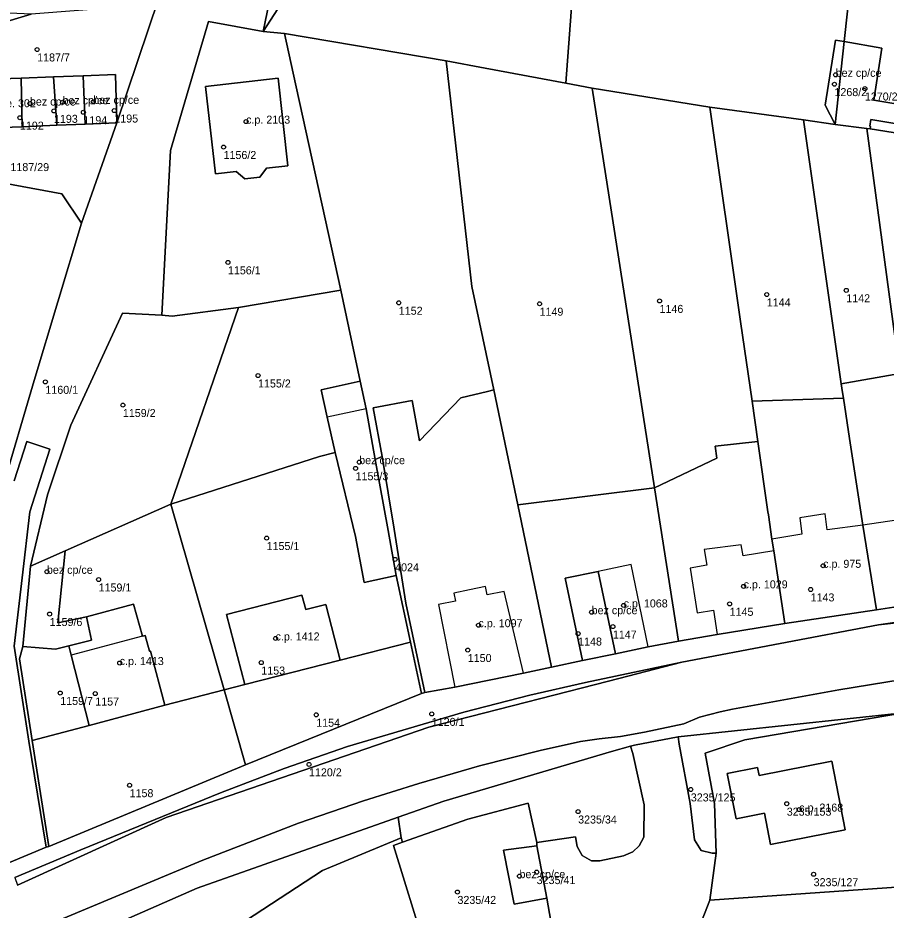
# Model space of a CAD drawing. Extents: x -878211 to -870363, y -1058464 to -1052522.
# Drawn here: x -875408.6 to -875300.1, y -1056399.9 to -1056288.4 of the extents above; entities that cross this region are included whole.
import ezdxf

# ---------------------------------------------------------------- set-up
doc = ezdxf.new("R2010")
doc.units = 0
for name, color, linetype in [('Definiční body', 7, 'Continuous'), ('Polygon budovy', 7, 'Continuous'), ('Polygon parcely', 7, 'Continuous')]:
    doc.layers.add(name, color=color, linetype=linetype)

msp = doc.modelspace()

# ---------------------------------------------------------------- linework, layer by layer
at = {"layer": 'Definiční body'}
for centre in [(-875406.21, -1056292.33994), (-875306.43, -1056295.49994), (-875306.58, -1056296.66994), (-875302.78, -1056297.21994), (-875407.11, -1056299.08994), (-875403.04, -1056298.92994), (-875399.19, -1056298.87994), (-875404.11, -1056300.00994), (-875400.43, -1056300.17994), (-875396.57, -1056299.96994), (-875408.36, -1056300.85994), (-875380.1, -1056301.34994), (-875382.92, -1056304.52994), (-875382.37, -1056318.93994), (-875305.1, -1056322.42994), (-875328.44, -1056323.75994), (-875315.04, -1056322.94994), (-875361.02, -1056323.98994), (-875343.43, -1056324.10994), (-875405.18, -1056333.86994), (-875378.61, -1056333.07994), (-875395.5, -1056336.76994), (-875365.97, -1056343.89994), (-875366.42, -1056344.66994), (-875377.54, -1056353.38994), (-875361.48, -1056356.04994), (-875307.99, -1056356.84994), (-875404.99, -1056357.59994), (-875398.53, -1056358.56994), (-875317.93, -1056359.41994), (-875309.56, -1056359.80994), (-875319.68, -1056361.60994), (-875404.65, -1056362.87994), (-875336.92, -1056362.64994), (-875332.92, -1056361.79994), (-875351.06, -1056364.26994), (-875334.27, -1056364.44994), (-875376.42, -1056365.92994), (-875338.61, -1056365.31994), (-875352.4, -1056367.37994), (-875395.89, -1056368.99994), (-875378.2, -1056368.94994), (-875403.33, -1056372.74994), (-875398.95, -1056372.81994), (-875371.34, -1056375.46994), (-875356.9, -1056375.35994), (-875372.24, -1056381.66994), (-875394.66, -1056384.26994), (-875324.53, -1056384.79994), (-875312.54, -1056386.57994), (-875310.99, -1056387.30994), (-875338.61, -1056387.55994), (-875343.79, -1056395.12994), (-875345.94, -1056395.62994), (-875309.18, -1056395.38994), (-875353.69, -1056397.60994)]:
    msp.add_circle(centre, 0.25, dxfattribs=at)
at = {"layer": 'Polygon budovy'}
for points in [[(-875305.37, -1056291.35), (-875306.43, -1056291.16), (-875307.75, -1056299.3), (-875306.51, -1056301.69), (-875302.54, -1056302.2), (-875302.13, -1056302.26), (-875302.08, -1056301.96), (-875302.18, -1056301.93), (-875302.04, -1056301.09), (-875295.32, -1056302.2), (-875294.92, -1056299.81), (-875301.66, -1056298.67), (-875300.65, -1056292.17)], [(-875400.44, -1056295.61), (-875404.17, -1056295.75), (-875403.75, -1056301.81), (-875400.2, -1056301.67)], [(-875400.44, -1056295.61), (-875400.2, -1056301.67), (-875396.26, -1056301.51), (-875396.44, -1056295.47)], [(-875408.21, -1056295.93), (-875412.12, -1056296.06), (-875411.83, -1056302.12), (-875408.09, -1056301.98)], [(-875408.09, -1056301.98), (-875403.75, -1056301.81), (-875404.17, -1056295.75), (-875408.21, -1056295.93)], [(-875376.1, -1056295.9), (-875385.18, -1056296.94), (-875383.94, -1056307.86), (-875381.34, -1056307.58), (-875380.24, -1056308.48), (-875378.37, -1056308.28), (-875377.55, -1056307.18), (-875374.88, -1056306.89)], [(-875369.99, -1056338.28), (-875368.95, -1056342.68), (-875366.42, -1056353.19), (-875365.35, -1056358.93), (-875361.33, -1056358.08), (-875362.36, -1056352.43), (-875363.96, -1056343.57), (-875365.1, -1056337.23)], [(-875314.41, -1056353.51), (-875314.15, -1056354.97), (-875312.78, -1056364.06), (-875301.34, -1056362.33), (-875303.05, -1056351.78), (-875307.48, -1056352.37), (-875307.75, -1056350.34), (-875310.9, -1056350.87), (-875310.66, -1056352.9)], [(-875298.81, -1056351.15), (-875303.05, -1056351.78), (-875301.34, -1056362.33), (-875294.27, -1056361.25), (-875295.94, -1056350.67)], [(-875324.61, -1056357.16), (-875323.75, -1056362.72), (-875321.7, -1056362.4), (-875321.25, -1056365.44), (-875312.78, -1056364.06), (-875314.15, -1056354.97), (-875317.99, -1056355.6), (-875318.22, -1056354.21), (-875322.86, -1056354.8), (-875322.52, -1056356.76)], [(-875407.06, -1056356.91), (-875407.98, -1056366.93), (-875403.93, -1056367.27), (-875402.25, -1056366.86), (-875399.41, -1056366.16), (-875400.04, -1056363.22), (-875403.63, -1056363.96), (-875402.69, -1056354.98)], [(-875329.85, -1056366.98), (-875331.97, -1056356.68), (-875336.12, -1056357.54), (-875333.92, -1056367.83)], [(-875340.21, -1056358.39), (-875338.05, -1056368.7), (-875333.92, -1056367.83), (-875336.12, -1056357.54)], [(-875350.18, -1056359.45), (-875352.17, -1056359.85), (-875354.16, -1056360.25), (-875353.95, -1056361.28), (-875356.06, -1056361.7), (-875354, -1056372.01), (-875345.45, -1056370.25), (-875347.86, -1056360.07), (-875349.97, -1056360.49)], [(-875382.53, -1056362.95), (-875380.25, -1056371.69), (-875368.36, -1056368.65), (-875370.14, -1056361.68), (-875372.65, -1056362.32), (-875373.13, -1056360.5)], [(-875392.16, -1056367.53), (-875392.7, -1056365.54), (-875393.06, -1056365.64), (-875401.95, -1056368.01), (-875399.69, -1056376.79), (-875390.25, -1056374.27), (-875392.06, -1056367.51)], [(-875319.97, -1056382.81), (-875318.88, -1056388.45), (-875315.34, -1056387.75), (-875314.57, -1056391.67), (-875305.25, -1056389.85), (-875306.91, -1056381.27), (-875315.99, -1056383.04), (-875316.18, -1056382.07)], [(-875343.77, -1056391.85), (-875347.92, -1056392.37), (-875346.61, -1056399.13), (-875342.54, -1056398.37)]]:
    msp.add_lwpolyline(points, close=True, dxfattribs=at)
at = {"layer": 'Polygon parcely'}
for points in [[(-875326.91, -1056259.71), (-875336.96, -1056259.61), (-875351.04, -1056263.15), (-875355.95, -1056264.37), (-875367.7, -1056267.24), (-875367.35, -1056268.89), (-875366.53, -1056272.35), (-875367.28, -1056273.5), (-875338.32, -1056272), (-875340.16, -1056296.55), (-875336.87, -1056297.17), (-875322.17, -1056299.55), (-875310.44, -1056301.13), (-875306.51, -1056301.69), (-875307.75, -1056299.3), (-875306.43, -1056291.16), (-875305.37, -1056291.35), (-875302.02, -1056260.98)], [(-875302.13, -1056302.26), (-875291.97, -1056303.86), (-875284.55, -1056269.53), (-875283.04, -1056262.38), (-875293.89, -1056266.2), (-875296.77, -1056265.83), (-875300.32, -1056264.94), (-875300.08, -1056262.78), (-875302.02, -1056260.98), (-875305.37, -1056291.35), (-875300.65, -1056292.17), (-875301.66, -1056298.67), (-875294.92, -1056299.81), (-875295.32, -1056302.2), (-875302.04, -1056301.09), (-875302.18, -1056301.93), (-875302.08, -1056301.96)], [(-875340.16, -1056296.55), (-875338.32, -1056272), (-875367.28, -1056273.5), (-875369.36, -1056276.73), (-875377.98, -1056290.07), (-875375.29, -1056290.34), (-875355.09, -1056293.74), (-875350.22, -1056294.66)], [(-875375.12, -1056276.33), (-875377.98, -1056290.07), (-875369.36, -1056276.73)], [(-875404.17, -1056295.75), (-875400.44, -1056295.61), (-875396.44, -1056295.47), (-875396.26, -1056301.51), (-875391.02, -1056285.88), (-875394.57, -1056286.98), (-875406.97, -1056287.91), (-875415.57, -1056290.51), (-875427.13, -1056290.52), (-875436.64, -1056290.52), (-875436.52, -1056296.94), (-875432.35, -1056296.72), (-875428.45, -1056296.53), (-875424.13, -1056296.4), (-875420.2, -1056296.3), (-875416.02, -1056296.19), (-875412.12, -1056296.06), (-875408.21, -1056295.93)], [(-875368.28, -1056322.39), (-875374.21, -1056295.28), (-875375.29, -1056290.34), (-875377.98, -1056290.07), (-875384.79, -1056288.85), (-875389.54, -1056304.94), (-875390.65, -1056325.55), (-875389.35, -1056325.65), (-875381.06, -1056324.59)], [(-875355.09, -1056293.74), (-875375.29, -1056290.34), (-875374.21, -1056295.28), (-875368.28, -1056322.39), (-875365.84, -1056333.77), (-875365.1, -1056337.23), (-875363.96, -1056343.57), (-875363.08, -1056343.2), (-875364.21, -1056337.1), (-875359.34, -1056336.21), (-875358.45, -1056341.25), (-875353.27, -1056335.87), (-875349.94, -1056335.06), (-875349.16, -1056334.87), (-875351.9, -1056321.95)], [(-875306.51, -1056301.69), (-875305.37, -1056291.35), (-875306.43, -1056291.16), (-875307.75, -1056299.3)], [(-875306.51, -1056301.69), (-875302.54, -1056302.2), (-875302.13, -1056302.26), (-875302.08, -1056301.96), (-875302.18, -1056301.93), (-875302.04, -1056301.09), (-875295.32, -1056302.2), (-875294.92, -1056299.81), (-875301.66, -1056298.67), (-875300.65, -1056292.17), (-875305.37, -1056291.35)], [(-875349.16, -1056334.87), (-875346.15, -1056349.25), (-875329.07, -1056347.09), (-875336.87, -1056297.17), (-875340.16, -1056296.55), (-875350.22, -1056294.66), (-875355.09, -1056293.74), (-875351.9, -1056321.95)], [(-875400.44, -1056295.61), (-875404.17, -1056295.75), (-875403.75, -1056301.81), (-875400.2, -1056301.67)], [(-875396.26, -1056301.51), (-875396.44, -1056295.47), (-875400.44, -1056295.61), (-875400.2, -1056301.67)], [(-875408.21, -1056295.93), (-875412.12, -1056296.06), (-875411.83, -1056302.12), (-875408.09, -1056301.98)], [(-875404.17, -1056295.75), (-875408.21, -1056295.93), (-875408.09, -1056301.98), (-875403.75, -1056301.81)], [(-875374.88, -1056306.89), (-875377.55, -1056307.18), (-875378.37, -1056308.28), (-875380.24, -1056308.48), (-875381.34, -1056307.58), (-875383.94, -1056307.86), (-875385.18, -1056296.94), (-875376.1, -1056295.9)], [(-875374.88, -1056306.89), (-875376.1, -1056295.9), (-875385.18, -1056296.94), (-875383.94, -1056307.86), (-875381.34, -1056307.58), (-875380.24, -1056308.48), (-875378.37, -1056308.28), (-875377.55, -1056307.18)], [(-875316.14, -1056341.31), (-875316.87, -1056336.26), (-875318.3, -1056326.31), (-875322.17, -1056299.55), (-875336.87, -1056297.17), (-875329.07, -1056347.09), (-875321.27, -1056343.39), (-875321.5, -1056341.9)], [(-875316.87, -1056336.26), (-875305.47, -1056335.92), (-875305.58, -1056335.18), (-875305.73, -1056334.13), (-875310.44, -1056301.13), (-875322.17, -1056299.55), (-875318.3, -1056326.31)], [(-875298.43, -1056332.82), (-875302.54, -1056302.2), (-875306.51, -1056301.69), (-875310.44, -1056301.13), (-875305.73, -1056334.13)], [(-875411.83, -1056302.12), (-875415.81, -1056302.28), (-875419.95, -1056302.44), (-875420.85, -1056302.48), (-875415.33, -1056308.13), (-875403.11, -1056310.38), (-875400.67, -1056314.05), (-875396.26, -1056301.51), (-875400.2, -1056301.67), (-875403.75, -1056301.81), (-875408.09, -1056301.98)], [(-875302.13, -1056302.26), (-875302.54, -1056302.2), (-875298.43, -1056332.82), (-875297.97, -1056336.46), (-875289.05, -1056336.42), (-875282.56, -1056335.7), (-875282.98, -1056331.54), (-875285.37, -1056305.08), (-875291.97, -1056303.86)], [(-875418.39, -1056347.04), (-875414.86, -1056347.4), (-875411.47, -1056347.74), (-875411.16, -1056348.42), (-875410.64, -1056347.42), (-875406.59, -1056333.71), (-875400.67, -1056314.05), (-875403.11, -1056310.38), (-875415.33, -1056308.13), (-875420.85, -1056302.48), (-875424.03, -1056302.61), (-875428.34, -1056302.78), (-875431.52, -1056302.9), (-875433.3, -1056345.53)], [(-875370.91, -1056343.17), (-875368.95, -1056342.68), (-875369.99, -1056338.28), (-875370.71, -1056334.85), (-875365.84, -1056333.77), (-875368.28, -1056322.39), (-875381.06, -1056324.59), (-875389.51, -1056349.15)], [(-875407.06, -1056356.91), (-875402.69, -1056354.98), (-875389.51, -1056349.15), (-875381.06, -1056324.59), (-875389.35, -1056325.65), (-875390.65, -1056325.55), (-875395.54, -1056325.27), (-875401.99, -1056339.26), (-875404.92, -1056347.98)], [(-875301.34, -1056362.33), (-875294.27, -1056361.25), (-875295.94, -1056350.67), (-875296.19, -1056349.09), (-875296.7, -1056345.43), (-875297.41, -1056340.42), (-875297.97, -1056336.46), (-875298.43, -1056332.82), (-875305.73, -1056334.13), (-875305.58, -1056335.18), (-875305.47, -1056335.92), (-875304.7, -1056340.96), (-875303.05, -1056351.78)], [(-875368.95, -1056342.68), (-875366.42, -1056353.19), (-875365.35, -1056358.93), (-875361.33, -1056358.08), (-875362.36, -1056352.43), (-875363.96, -1056343.57), (-875365.1, -1056337.23), (-875365.84, -1056333.77), (-875370.71, -1056334.85), (-875369.99, -1056338.28)], [(-875354, -1056372.01), (-875345.45, -1056370.25), (-875341.92, -1056369.5), (-875346.15, -1056349.25), (-875349.16, -1056334.87), (-875349.94, -1056335.06), (-875353.27, -1056335.87), (-875358.45, -1056341.25), (-875359.34, -1056336.21), (-875364.21, -1056337.1), (-875363.08, -1056343.2), (-875361.59, -1056352.27), (-875360.14, -1056361.53), (-875357.78, -1056372.69)], [(-875316.14, -1056341.31), (-875314.89, -1056350.12), (-875314.83, -1056350.46), (-875314.41, -1056353.51), (-875314.15, -1056354.97), (-875312.78, -1056364.06), (-875301.34, -1056362.33), (-875303.05, -1056351.78), (-875304.7, -1056340.96), (-875305.47, -1056335.92), (-875316.87, -1056336.26)], [(-875326.08, -1056366.26), (-875321.25, -1056365.44), (-875312.78, -1056364.06), (-875314.15, -1056354.97), (-875314.41, -1056353.51), (-875314.83, -1056350.46), (-875314.89, -1056350.12), (-875316.14, -1056341.31), (-875321.5, -1056341.9), (-875321.27, -1056343.39), (-875329.07, -1056347.09)], [(-875361.33, -1056358.08), (-875365.35, -1056358.93), (-875366.42, -1056353.19), (-875368.95, -1056342.68), (-875370.91, -1056343.17), (-875389.51, -1056349.15), (-875382.86, -1056372.36), (-875380.25, -1056371.69), (-875382.53, -1056362.95), (-875373.13, -1056360.5), (-875372.65, -1056362.32), (-875370.14, -1056361.68), (-875368.36, -1056368.65), (-875359.55, -1056366.4)], [(-875363.08, -1056343.2), (-875363.96, -1056343.57), (-875362.36, -1056352.43), (-875361.33, -1056358.08), (-875359.55, -1056366.4), (-875358.17, -1056372.82), (-875357.78, -1056372.69), (-875360.14, -1056361.53), (-875361.59, -1056352.27)], [(-875346.15, -1056349.25), (-875341.92, -1056369.5), (-875338.05, -1056368.7), (-875340.21, -1056358.39), (-875336.12, -1056357.54), (-875333.92, -1056367.83), (-875329.85, -1056366.98), (-875326.08, -1056366.26), (-875329.07, -1056347.09)], [(-875403.63, -1056363.96), (-875400.04, -1056363.22), (-875394.17, -1056361.65), (-875393.06, -1056365.64), (-875392.7, -1056365.54), (-875392.16, -1056367.53), (-875392.06, -1056367.51), (-875390.25, -1056374.27), (-875382.86, -1056372.36), (-875389.51, -1056349.15), (-875402.69, -1056354.98)], [(-875402.25, -1056366.86), (-875399.41, -1056366.16), (-875400.04, -1056363.22), (-875403.63, -1056363.96), (-875402.69, -1056354.98), (-875407.06, -1056356.91), (-875407.98, -1056366.93), (-875403.93, -1056367.27)], [(-875333.92, -1056367.83), (-875336.12, -1056357.54), (-875340.21, -1056358.39), (-875338.05, -1056368.7)], [(-875301.06, -1056364.21), (-875241.87, -1056357.54), (-875267.21, -1056359.9), (-875277.03, -1056360.91), (-875283.21, -1056361.69)], [(-875382.53, -1056362.95), (-875380.25, -1056371.69), (-875368.36, -1056368.65), (-875370.14, -1056361.68), (-875372.65, -1056362.32), (-875373.13, -1056360.5)], [(-875399.69, -1056376.79), (-875390.25, -1056374.27), (-875392.06, -1056367.51), (-875392.16, -1056367.53), (-875392.7, -1056365.54), (-875393.06, -1056365.64), (-875394.17, -1056361.65), (-875400.04, -1056363.22), (-875399.41, -1056366.16), (-875402.25, -1056366.86), (-875401.95, -1056368.01)], [(-875407.98, -1056366.93), (-875408.42, -1056368.46), (-875406.82, -1056378.69), (-875399.69, -1056376.79), (-875401.95, -1056368.01), (-875402.25, -1056366.86), (-875403.93, -1056367.27)], [(-875368.36, -1056368.65), (-875380.25, -1056371.69), (-875382.86, -1056372.36), (-875380.18, -1056381.71), (-875358.17, -1056372.82), (-875359.55, -1056366.4)], [(-875409.01, -1056395.8), (-875408.68, -1056396.75), (-875390.07, -1056388.31), (-875357.27, -1056377.02), (-875336.44, -1056371.66), (-875333.52, -1056370.91), (-875325.65, -1056368.89), (-875337.67, -1056371.42), (-875344.63, -1056373.02), (-875352.88, -1056375.12), (-875367.42, -1056379.44), (-875375.34, -1056382.19), (-875383.29, -1056385.23), (-875400.76, -1056392.35)], [(-875406.82, -1056378.69), (-875404.76, -1056391.92), (-875380.18, -1056381.71), (-875382.86, -1056372.36), (-875390.25, -1056374.27), (-875399.69, -1056376.79)], [(-875326.1, -1056378.2), (-875325.97, -1056379.15), (-875324.63, -1056386.54), (-875324.06, -1056391.07), (-875323.25, -1056392.41), (-875321.87, -1056392.75), (-875321.37, -1056392.77), (-875321.58, -1056386.56), (-875322.73, -1056380.24), (-875317.77, -1056378.59), (-875297.94, -1056375.24)], [(-875296.47, -1056396.84), (-875297.94, -1056375.24), (-875317.77, -1056378.59), (-875322.73, -1056380.24), (-875321.58, -1056386.56), (-875321.37, -1056392.77), (-875322.15, -1056398.63)], [(-875332.07, -1056379.37), (-875334.45, -1056380.07), (-875355.39, -1056386.25), (-875361.1, -1056388.27), (-875360.73, -1056390.83), (-875360.54, -1056391.37), (-875352.41, -1056388.49), (-875344.85, -1056386.51), (-875343.75, -1056391.44), (-875338.92, -1056390.7), (-875338.73, -1056391.94), (-875338.12, -1056393.03), (-875336.94, -1056393.7), (-875335.89, -1056393.73), (-875332.96, -1056393.1), (-875331.76, -1056392.58), (-875330.97, -1056391.83), (-875330.42, -1056390.75), (-875330.37, -1056386.7), (-875331.79, -1056380.31)], [(-875314.57, -1056391.67), (-875305.25, -1056389.85), (-875306.91, -1056381.27), (-875315.99, -1056383.04), (-875316.18, -1056382.07), (-875319.97, -1056382.81), (-875318.88, -1056388.45), (-875315.34, -1056387.75)], [(-875314.57, -1056391.67), (-875315.34, -1056387.75), (-875318.88, -1056388.45), (-875319.97, -1056382.81), (-875316.18, -1056382.07), (-875315.99, -1056383.04), (-875306.91, -1056381.27), (-875305.25, -1056389.85)], [(-875343.75, -1056391.44), (-875344.85, -1056386.51), (-875352.41, -1056388.49), (-875360.54, -1056391.37), (-875361.7, -1056391.81), (-875357.73, -1056404.64), (-875341.85, -1056402.19), (-875342.54, -1056398.37), (-875346.61, -1056399.13), (-875347.92, -1056392.37), (-875343.77, -1056391.85)], [(-875460.24, -1056430.33), (-875515.54, -1056452.4), (-875503.27, -1056450.06), (-875497.4, -1056449.08), (-875474.74, -1056447.47), (-875471.06, -1056446.94), (-875473.08, -1056441.99), (-875445.75, -1056437.14), (-875438.06, -1056434.12), (-875434.01, -1056431.54), (-875422.98, -1056424.06), (-875409.72, -1056417.39), (-875388.72, -1056406.79), (-875370.54, -1056394.92), (-875360.73, -1056390.83), (-875361.1, -1056388.27), (-875386.22, -1056397.14), (-875418.32, -1056411.2)], [(-875388.59, -1056413.05), (-875357.73, -1056404.64), (-875361.7, -1056391.81), (-875360.54, -1056391.37), (-875360.73, -1056390.83), (-875370.54, -1056394.92), (-875388.72, -1056406.79)], [(-875343.77, -1056391.85), (-875347.92, -1056392.37), (-875346.61, -1056399.13), (-875342.54, -1056398.37)], [(-875294.84, -1056413.39), (-875295.85, -1056405.83), (-875296.47, -1056396.84), (-875322.15, -1056398.63), (-875323.47, -1056402.06), (-875324.32, -1056403.89), (-875327.7, -1056411.12), (-875330.72, -1056421.11)]]:
    msp.add_lwpolyline(points, close=True, dxfattribs=at)
for points in [[(-875409.07, -1056346.25), (-875407.48, -1056341.33), (-875404.62, -1056342.29), (-875407.12, -1056350.09), (-875408.09, -1056358.35), (-875409.09, -1056366.89), (-875407.24, -1056378.74), (-875405.09, -1056391.99), (-875404.76, -1056391.92), (-875406.82, -1056378.69), (-875408.42, -1056368.46), (-875407.98, -1056366.93), (-875407.06, -1056356.91), (-875404.92, -1056347.98), (-875401.99, -1056339.26), (-875395.54, -1056325.27), (-875390.65, -1056325.55), (-875389.54, -1056304.94), (-875384.79, -1056288.85), (-875377.98, -1056290.07), (-875375.12, -1056276.33)], [(-875415.57, -1056290.51), (-875406.97, -1056287.91), (-875438.96, -1056286.41)], [(-875391.02, -1056285.88), (-875396.26, -1056301.51), (-875400.67, -1056314.05), (-875406.59, -1056333.71), (-875410.64, -1056347.42)], [(-875405.09, -1056391.99), (-875407.24, -1056378.74), (-875409.09, -1056366.89), (-875408.09, -1056358.35), (-875407.12, -1056350.09), (-875404.62, -1056342.29), (-875407.48, -1056341.33), (-875409.07, -1056346.25)], [(-875409.01, -1056395.8), (-875400.76, -1056392.35), (-875383.29, -1056385.23), (-875375.34, -1056382.19), (-875367.42, -1056379.44), (-875352.88, -1056375.12), (-875344.63, -1056373.02), (-875337.67, -1056371.42), (-875325.65, -1056368.89), (-875301.06, -1056364.21), (-875283.21, -1056361.69), (-875277.03, -1056360.91), (-875267.21, -1056359.9), (-875241.87, -1056357.54), (-875215.85, -1056355.72), (-875209.72, -1056355.65), (-875201.3, -1056355.92), (-875193.92, -1056356.66), (-875178.63, -1056358.65), (-875156.63, -1056364.33), (-875140.69, -1056370.83), (-875124.79, -1056378.79)], [(-875178.63, -1056358.65), (-875193.92, -1056356.66), (-875215.85, -1056355.72), (-875241.87, -1056357.54), (-875301.06, -1056364.21), (-875325.65, -1056368.89), (-875333.52, -1056370.91), (-875336.44, -1056371.66), (-875357.27, -1056377.02), (-875390.07, -1056388.31), (-875408.68, -1056396.75)], [(-875294.27, -1056361.25), (-875301.34, -1056362.33), (-875312.78, -1056364.06), (-875321.25, -1056365.44), (-875326.08, -1056366.26), (-875329.85, -1056366.98), (-875333.92, -1056367.83), (-875338.05, -1056368.7), (-875341.92, -1056369.5), (-875345.45, -1056370.25), (-875354, -1056372.01), (-875357.78, -1056372.69), (-875358.17, -1056372.82), (-875380.18, -1056381.71), (-875404.76, -1056391.92), (-875405.09, -1056391.99), (-875409.65, -1056393.92)], [(-875420.94, -1056408.41), (-875385.5, -1056393.63), (-875373.56, -1056389.01), (-875365.42, -1056386.2), (-875358.5, -1056384.03), (-875350.93, -1056381.86), (-875343.34, -1056379.91), (-875338.3, -1056378.82), (-875335.97, -1056378.46), (-875333.32, -1056378.17), (-875330.31, -1056377.63), (-875325.4, -1056376.6), (-875323.46, -1056375.78), (-875320.87, -1056375.1), (-875319.32, -1056374.78), (-875306.02, -1056372.36), (-875292.24, -1056370.08)], [(-875292.24, -1056370.08), (-875306.02, -1056372.36), (-875319.32, -1056374.78), (-875320.87, -1056375.1), (-875323.46, -1056375.78), (-875325.4, -1056376.6), (-875330.31, -1056377.63), (-875333.32, -1056378.17), (-875335.97, -1056378.46), (-875338.3, -1056378.82), (-875343.34, -1056379.91), (-875350.93, -1056381.86), (-875358.5, -1056384.03), (-875365.42, -1056386.2), (-875373.56, -1056389.01), (-875385.5, -1056393.63), (-875420.94, -1056408.41)], [(-875418.32, -1056411.2), (-875386.22, -1056397.14), (-875361.1, -1056388.27), (-875355.39, -1056386.25), (-875334.45, -1056380.07), (-875332.07, -1056379.37), (-875331.56, -1056379.27), (-875326.1, -1056378.2), (-875297.94, -1056375.24)], [(-875323.47, -1056402.06), (-875322.15, -1056398.63), (-875321.37, -1056392.77), (-875321.87, -1056392.75), (-875323.25, -1056392.41), (-875324.06, -1056391.07), (-875324.63, -1056386.54), (-875325.97, -1056379.15), (-875326.1, -1056378.2), (-875331.56, -1056379.27), (-875332.07, -1056379.37), (-875331.79, -1056380.31), (-875330.37, -1056386.7), (-875330.42, -1056390.75), (-875330.97, -1056391.83), (-875331.76, -1056392.58), (-875332.96, -1056393.1), (-875335.89, -1056393.73), (-875336.94, -1056393.7), (-875338.12, -1056393.03), (-875338.73, -1056391.94), (-875338.92, -1056390.7), (-875343.75, -1056391.44), (-875343.77, -1056391.85), (-875342.54, -1056398.37), (-875341.85, -1056402.19)], [(-875409.65, -1056393.92), (-875405.09, -1056391.99)]]:
    msp.add_lwpolyline(points, dxfattribs=at)

# ---------------------------------------------------------------- texts
at = {"layer": 'Definiční body'}
for s, p in [('1187/7', (-875406.21, -1056293.829)), ('bez cp/ce', (-875306.43, -1056295.75)), ('1268/2', (-875306.58, -1056298.159)), ('1270/2', (-875302.78, -1056298.709)), ('c.e. 302', (-875411.13, -1056299.55)), ('bez cp/ce', (-875407.11, -1056299.34)), ('bez cp/ce', (-875403.04, -1056299.179)), ('bez cp/ce', (-875399.19, -1056299.129)), ('1193', (-875404.11, -1056301.499)), ('1194', (-875400.43, -1056301.669)), ('1195', (-875396.57, -1056301.459)), ('c.p. 2103', (-875380.1, -1056301.6)), ('1192', (-875408.36, -1056302.349)), ('1156/2', (-875382.92, -1056306.019)), ('1187/29', (-875409.55, -1056307.529)), ('1156/1', (-875382.37, -1056320.429)), ('1144', (-875315.04, -1056324.439)), ('1142', (-875305.1, -1056323.919)), ('1152', (-875361.02, -1056325.479)), ('1149', (-875343.43, -1056325.599)), ('1146', (-875328.44, -1056325.249)), ('1155/2', (-875378.61, -1056334.569)), ('1160/1', (-875405.18, -1056335.359)), ('1159/2', (-875395.5, -1056338.259)), ('bez cp/ce', (-875365.97, -1056344.149)), ('1155/3', (-875366.42, -1056346.159)), ('1155/1', (-875377.54, -1056354.879)), ('bez cp/ce', (-875404.99, -1056357.85)), ('4024', (-875361.48, -1056357.539)), ('c.p. 975', (-875307.99, -1056357.1)), ('1159/1', (-875398.53, -1056360.059)), ('c.p. 1029', (-875317.93, -1056359.669)), ('1143', (-875309.56, -1056361.299)), ('c.p. 1068', (-875332.92, -1056362.05)), ('bez cp/ce', (-875336.92, -1056362.899)), ('1145', (-875319.68, -1056363.099)), ('1159/6', (-875404.65, -1056364.369)), ('c.p. 1097', (-875351.06, -1056364.52)), ('c.p. 1412', (-875376.42, -1056366.179)), ('1148', (-875338.61, -1056366.809)), ('1147', (-875334.27, -1056365.939)), ('1150', (-875352.4, -1056368.869)), ('c.p. 1413', (-875395.89, -1056369.25)), ('1153', (-875378.2, -1056370.439)), ('1159/7', (-875403.33, -1056374.239)), ('1157', (-875398.95, -1056374.309)), ('1154', (-875371.34, -1056376.959)), ('1120/1', (-875356.9, -1056376.849)), ('1120/2', (-875372.24, -1056383.159)), ('1158', (-875394.66, -1056385.759)), ('3235/125', (-875324.53, -1056386.289)), ('3235/153', (-875312.54, -1056388.069)), ('c.p. 2168', (-875310.99, -1056387.56)), ('3235/34', (-875338.61, -1056389.049)), ('bez cp/ce', (-875345.94, -1056395.879)), ('3235/41', (-875343.79, -1056396.619)), ('3235/127', (-875309.18, -1056396.879)), ('3235/42', (-875353.69, -1056399.099))]:
    msp.add_text(s, height=0.999996, dxfattribs=at).set_placement(p)

doc.saveas('drawing.dxf')
